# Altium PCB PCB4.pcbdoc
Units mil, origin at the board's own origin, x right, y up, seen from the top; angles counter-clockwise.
Board outline 1949.7 x 1974.5 mil, 4 copper layers (Top Layer, Inner1, Inner2, Bottom Layer); 13 components, 9 nets, 52 pads, 33 vias.
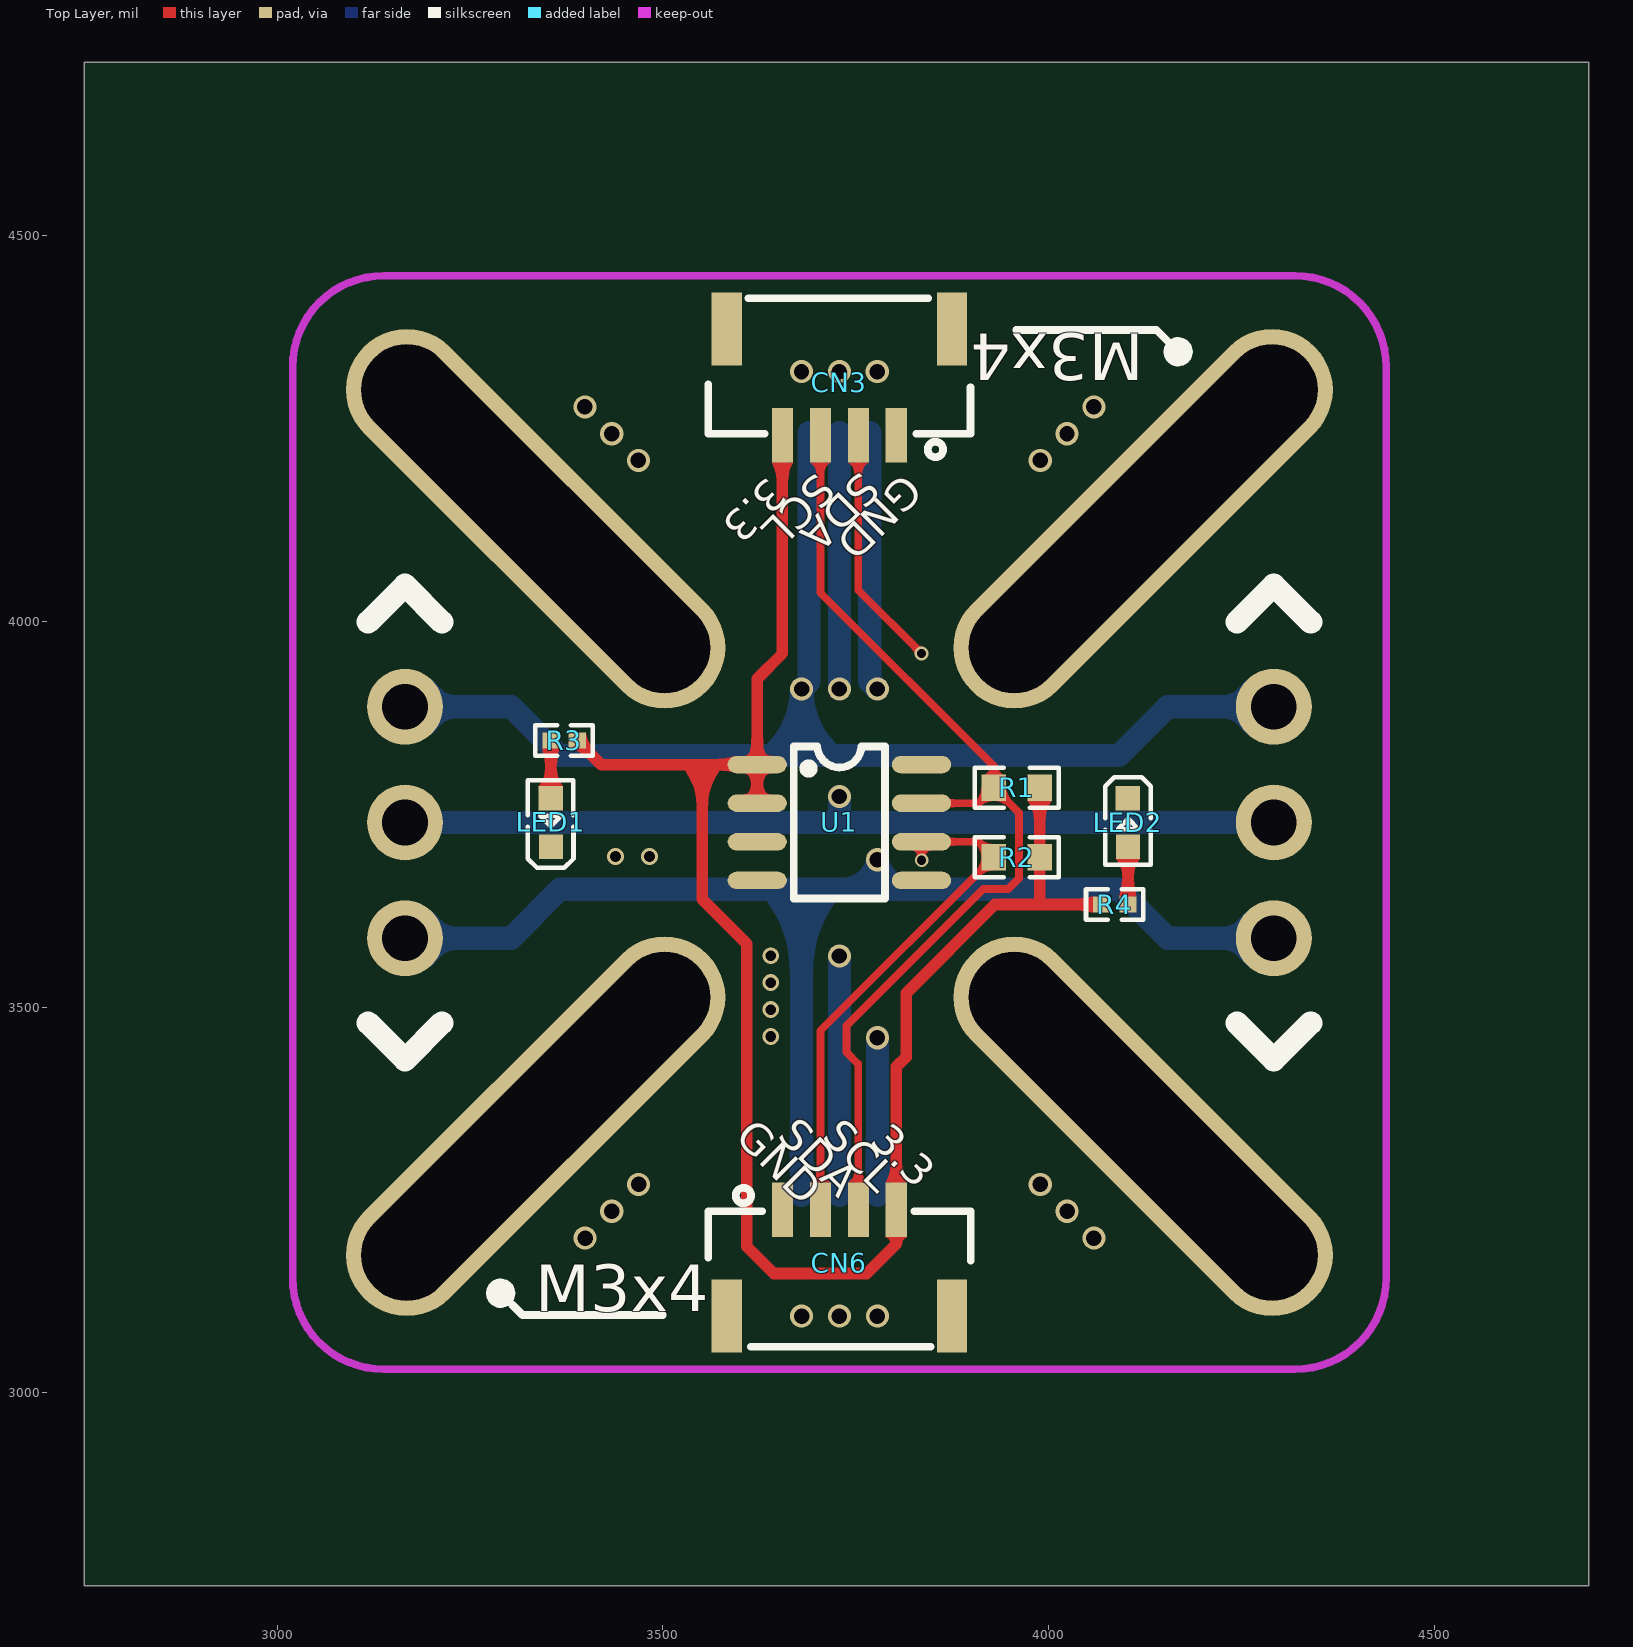
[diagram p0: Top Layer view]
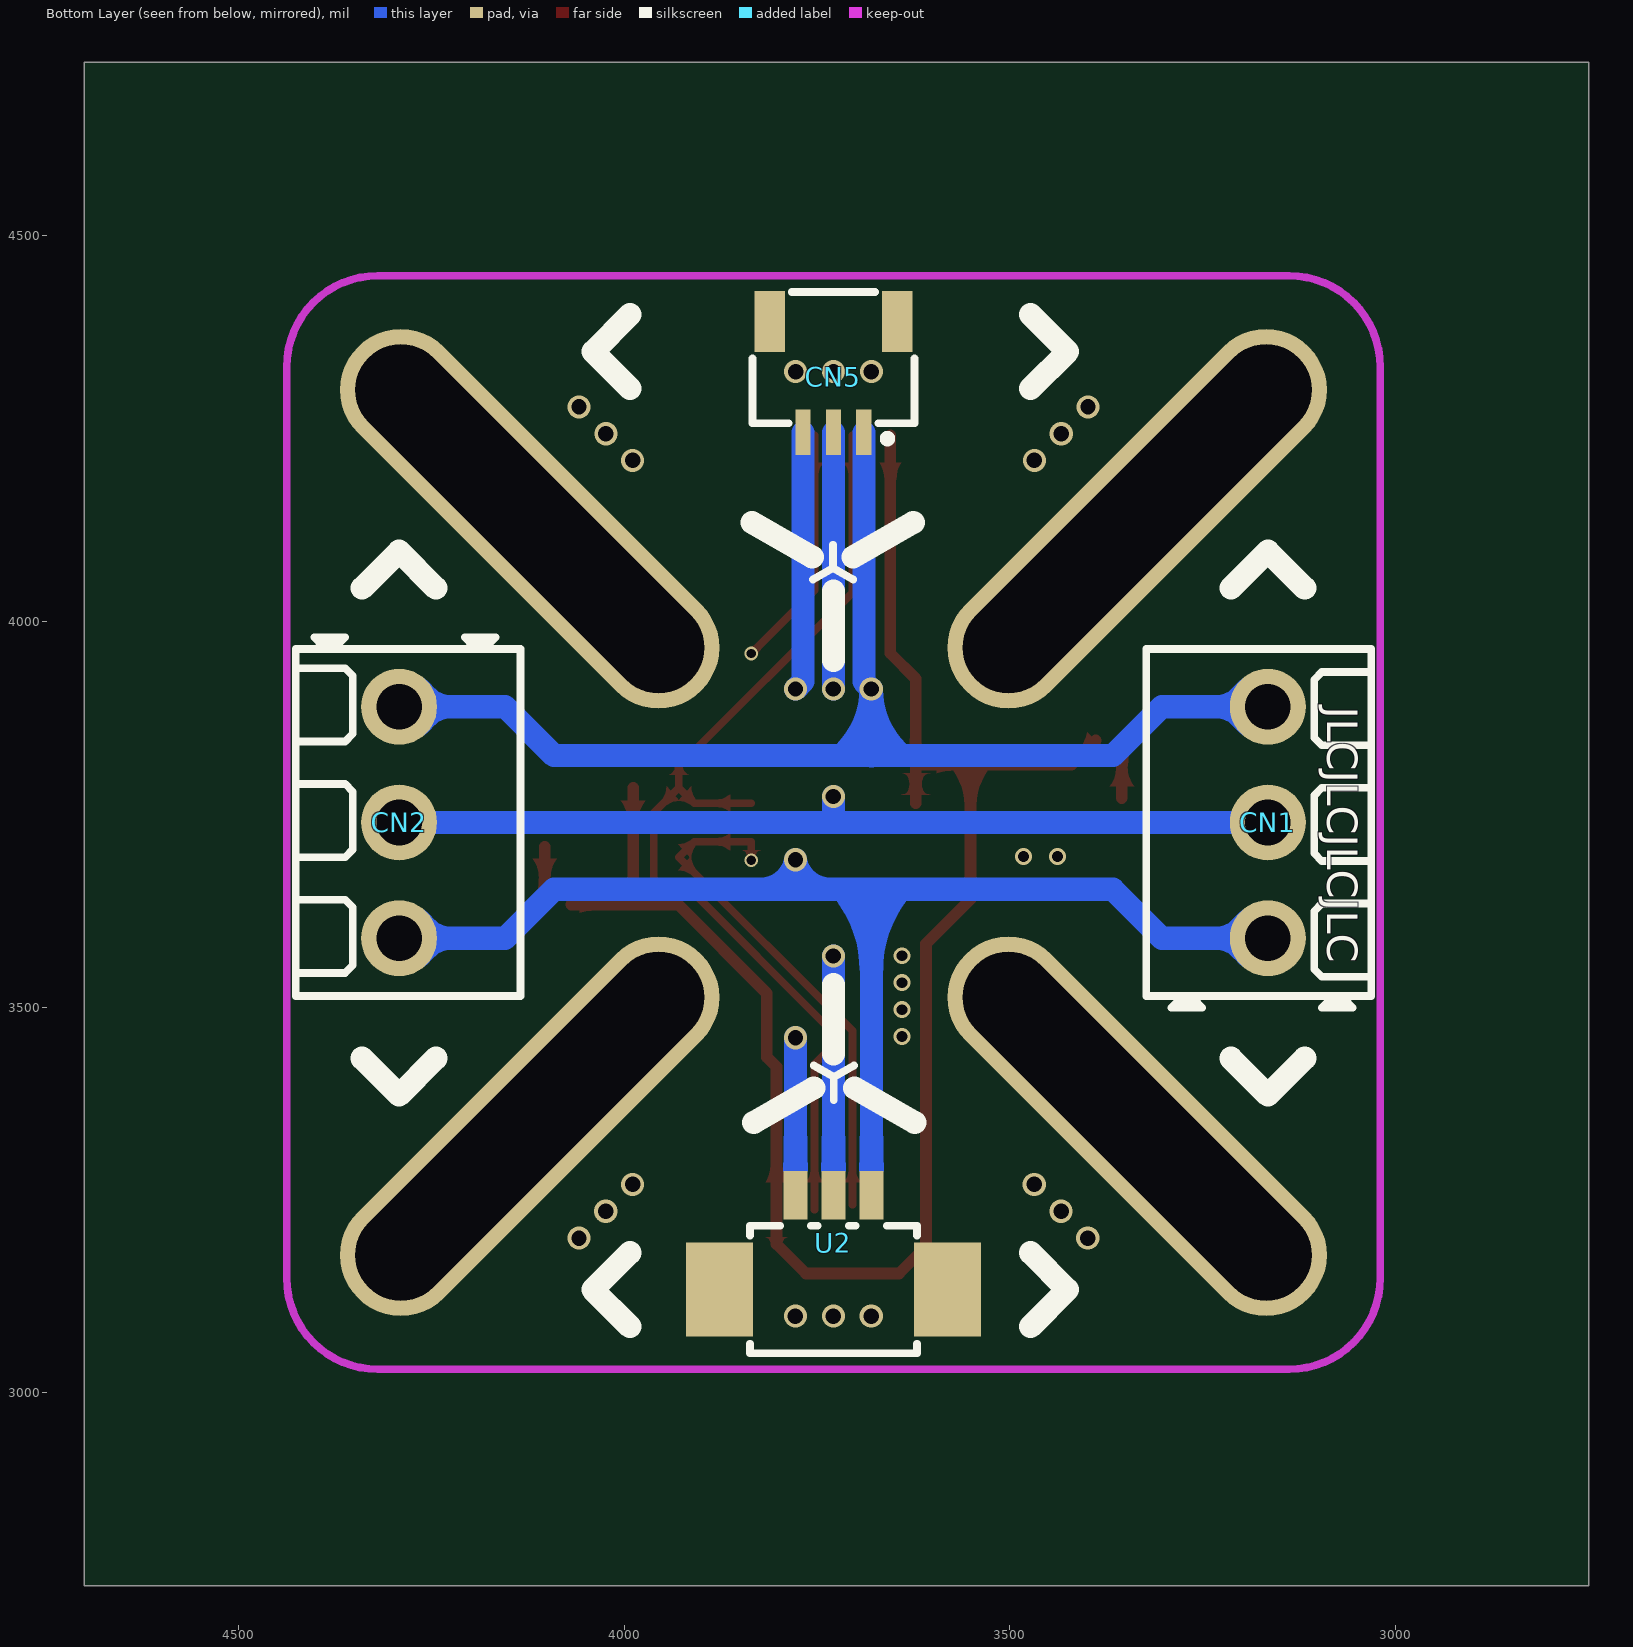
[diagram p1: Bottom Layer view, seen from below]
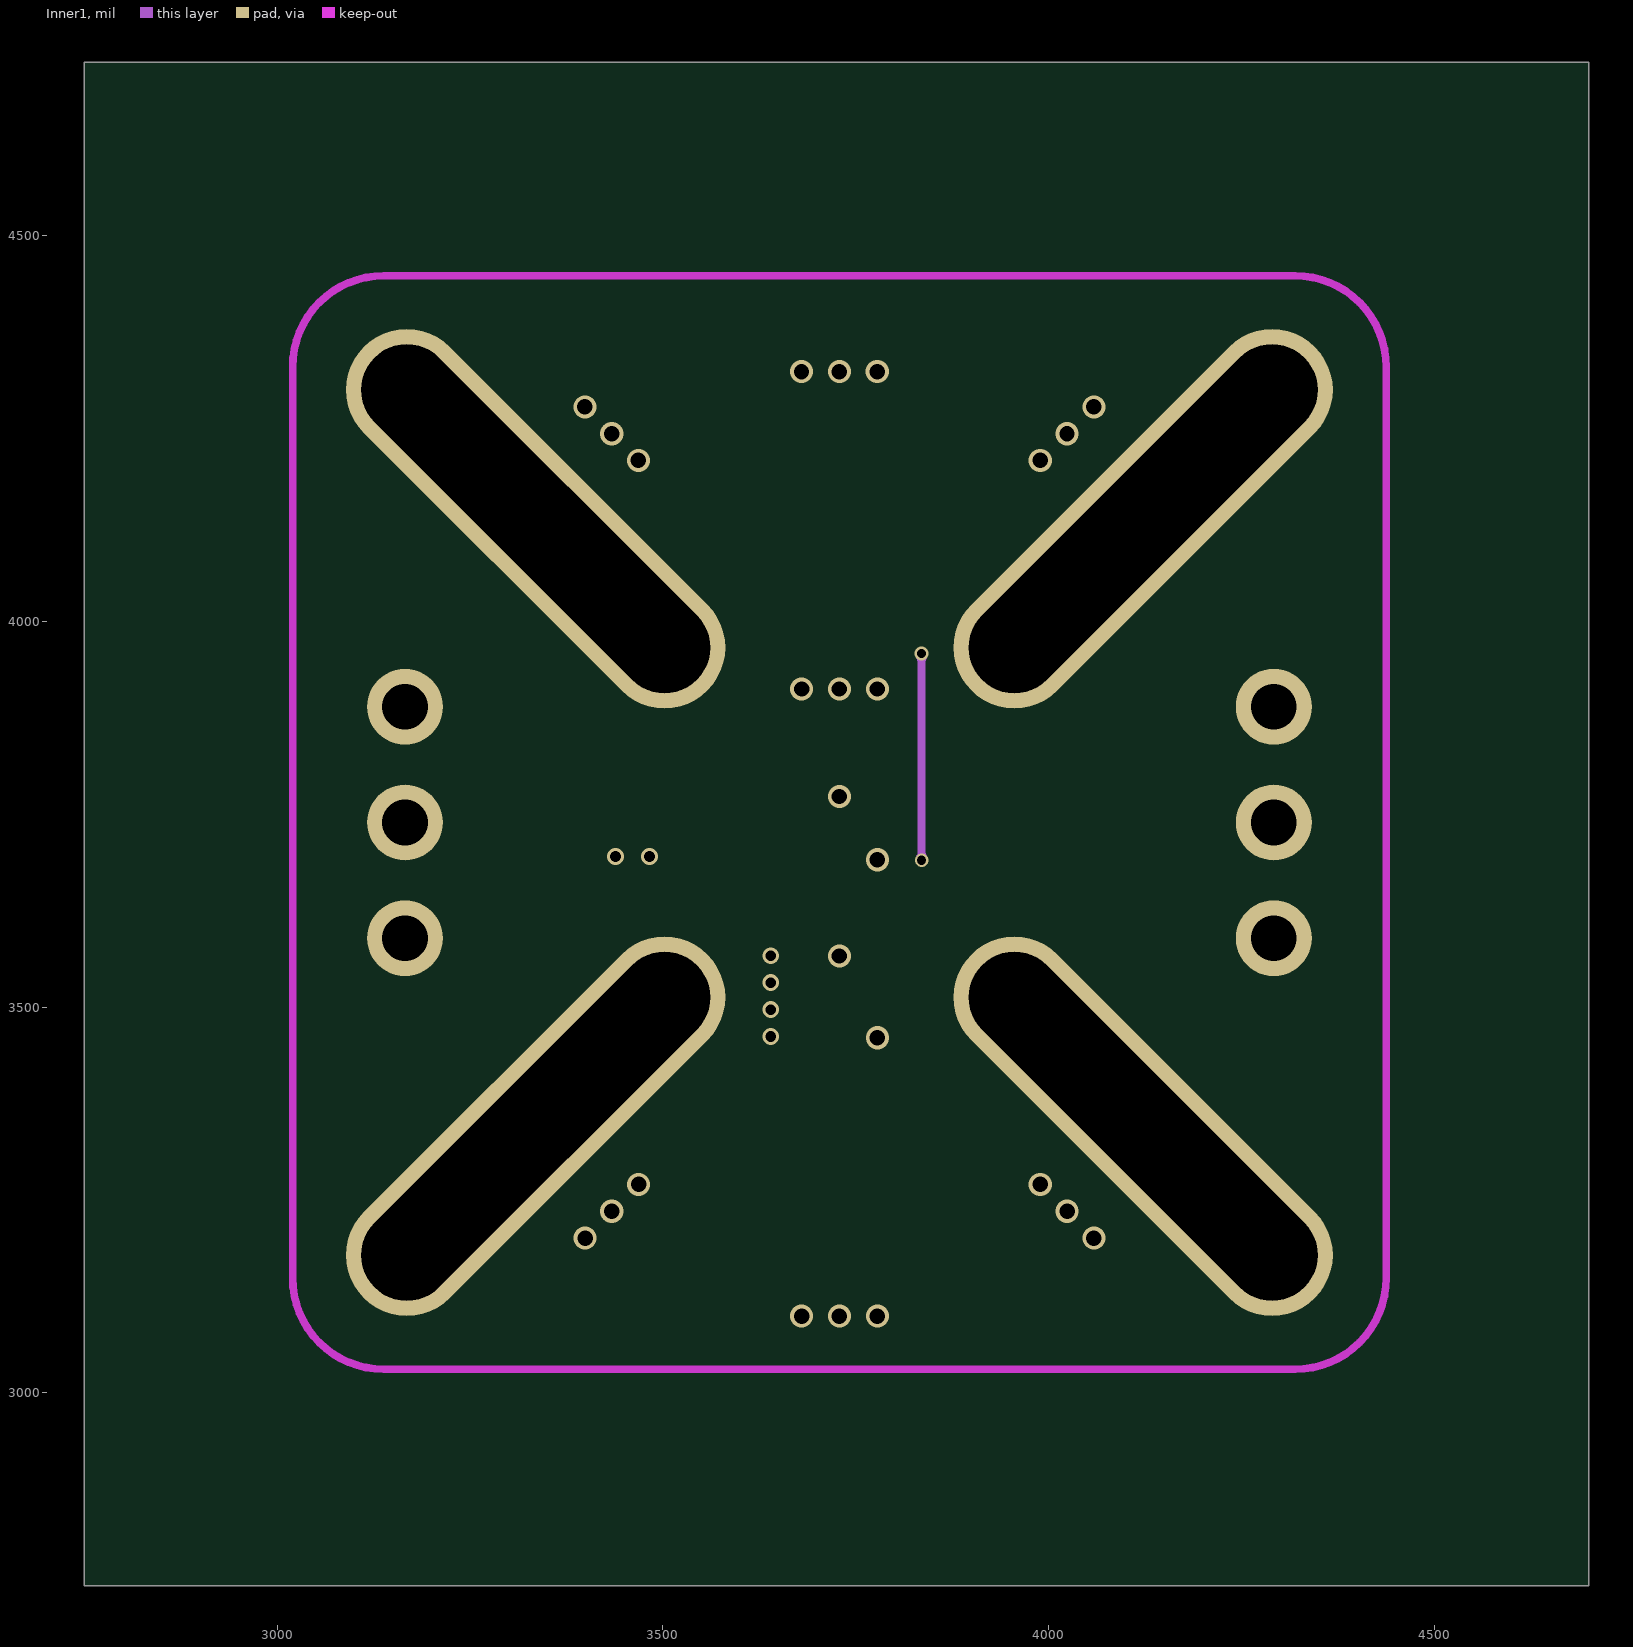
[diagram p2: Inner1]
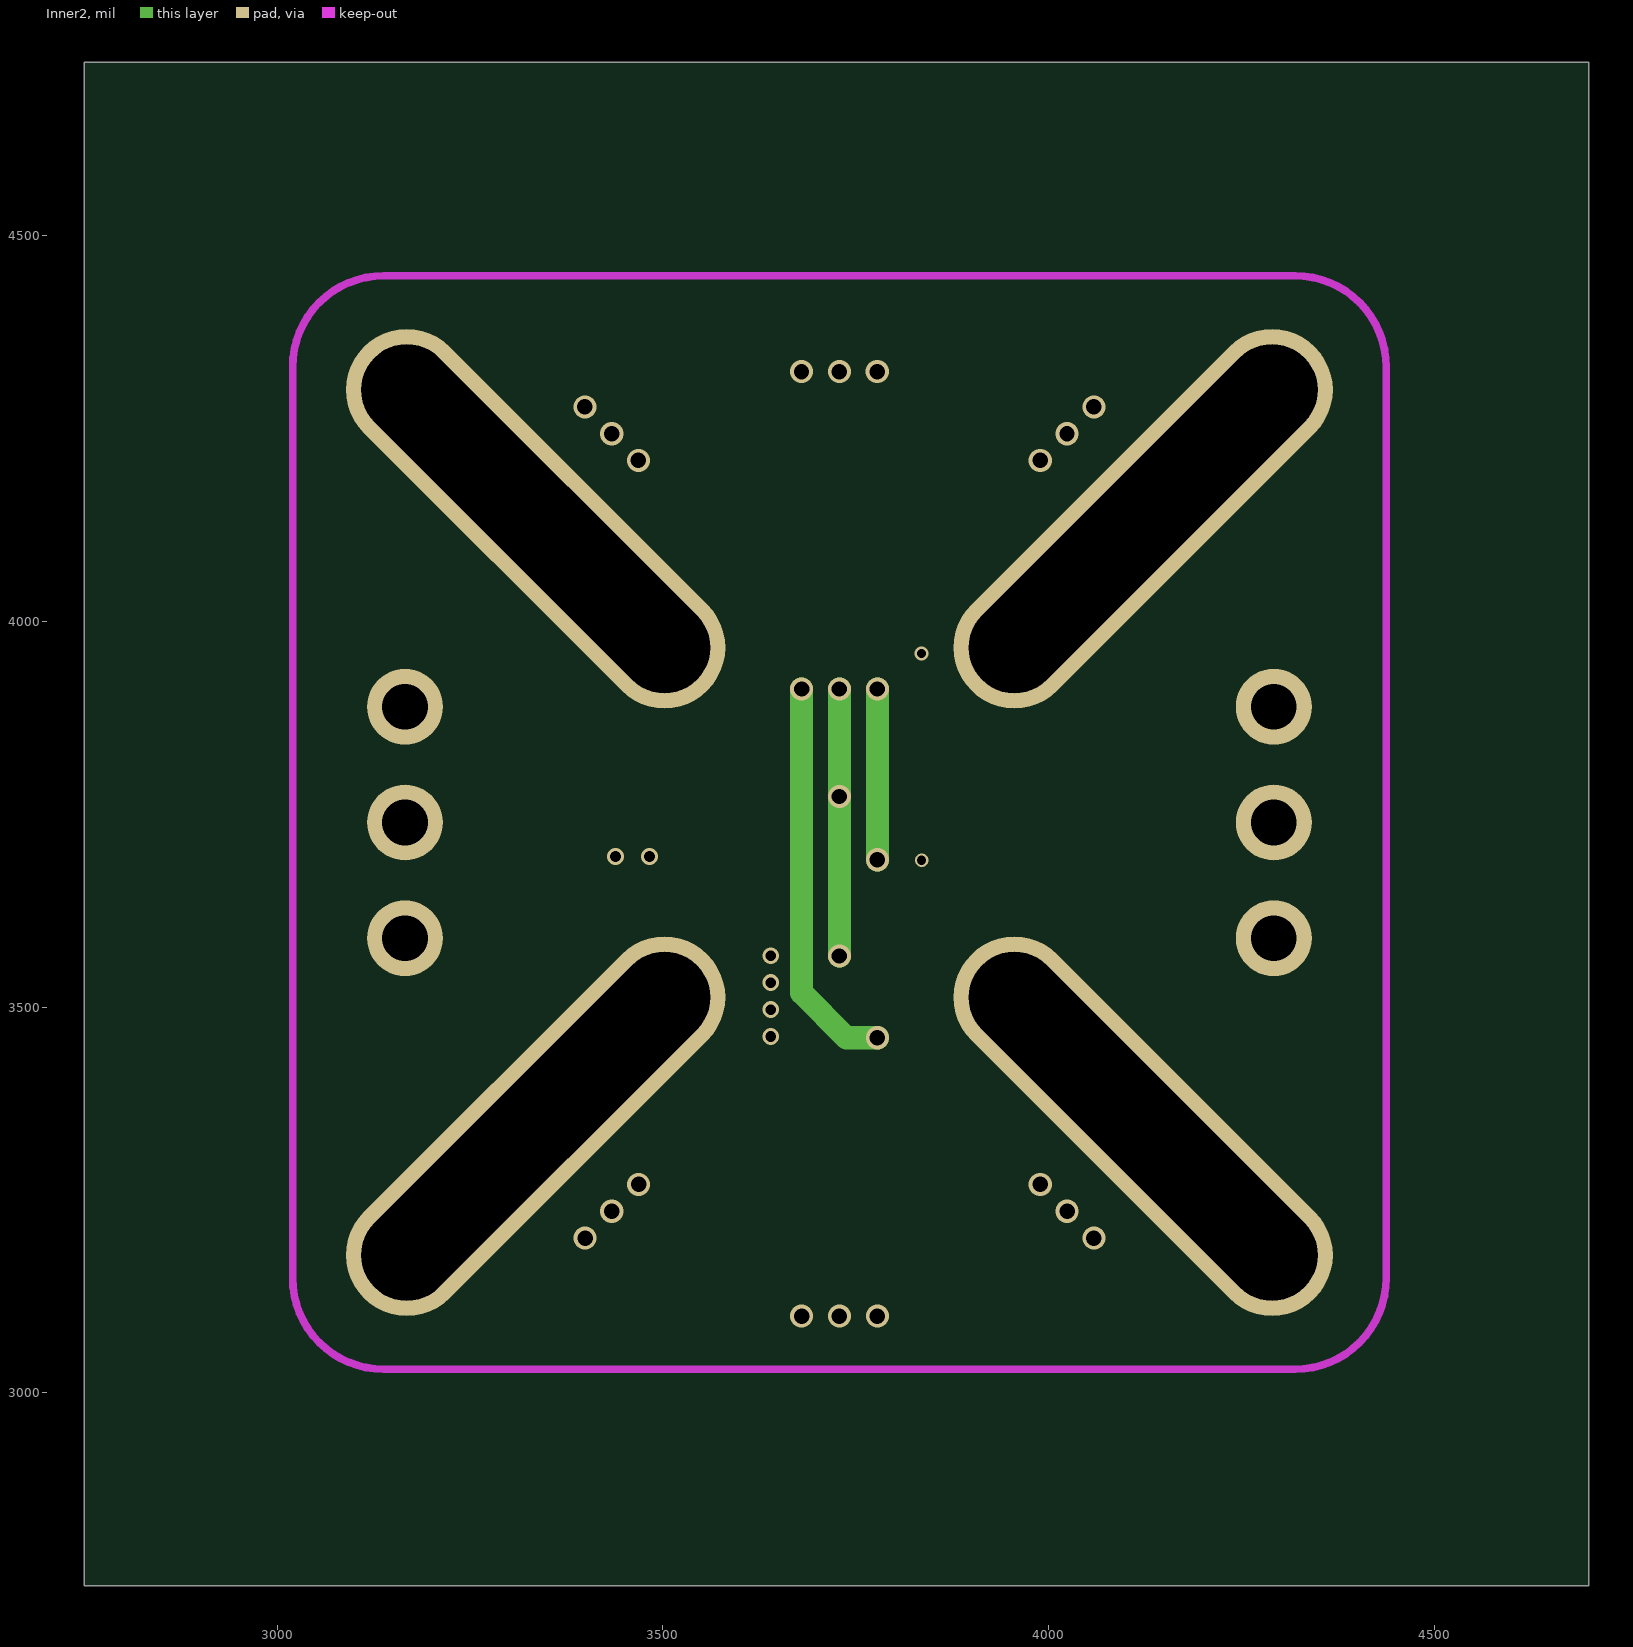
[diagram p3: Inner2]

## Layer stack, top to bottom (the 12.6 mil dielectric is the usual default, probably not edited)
Top Layer: signal copper (thickness not stored)
Dielectric: dielectric 12.6, FR-4, Dk 4.8
Inner1: signal copper (thickness not stored)
Dielectric: dielectric 12.6, FR-4, Dk 4.8
Inner2: signal copper (thickness not stored)
Dielectric: dielectric 12.6, FR-4, Dk 4.8
Bottom Layer: signal copper (thickness not stored)

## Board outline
4699.7,2750 2750,2750 2750,4724.5 4699.7,4724.5

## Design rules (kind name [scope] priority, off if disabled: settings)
BoardOutlineClearance copperThickness1oz [All] p0: genericclearance=10 ignorepadtopadclearanceinfootprint=FALSE except(0: Arc-SplitContinuation Track-SplitContinuation SMDPad-SplitContinuation THPad-SplitContinuation Via-SplitContinuation Fill-SplitContinuation Poly-SplitContinuation Region-SplitContinuation Text-SplitContinuation; 6: Track-CutoutEdge SMDPad-CutoutEdge THPad-CutoutEdge Via-CutoutEdge Region-CutoutEdge; 11.8: Track-OutlineEdge SMDPad-OutlineEdge THPad-OutlineEdge Via-OutlineEdge Fill-OutlineEdge Region-OutlineEdge Poly-OutlineEdge Text-OutlineEdge Fill-CutoutEdge)
BoardOutlineClearance copperThickness2oz [All] p0: genericclearance=10 ignorepadtopadclearanceinfootprint=FALSE except(0: Arc-SplitContinuation Track-SplitContinuation SMDPad-SplitContinuation THPad-SplitContinuation Via-SplitContinuation Fill-SplitContinuation Poly-SplitContinuation Region-SplitContinuation Text-SplitContinuation; 6: Track-CutoutEdge SMDPad-CutoutEdge THPad-CutoutEdge Via-CutoutEdge Region-CutoutEdge; 11.8: Track-OutlineEdge SMDPad-OutlineEdge THPad-OutlineEdge Via-OutlineEdge Fill-OutlineEdge Region-OutlineEdge Poly-OutlineEdge Text-OutlineEdge Fill-CutoutEdge)
Clearance copperThickness1oz [(InNet('W') OR InNet('V') OR InNet('U') OR InNet('+3.3V_1') OR InNet('SCL') OR InNet('SDA') OR InNet('DGND') OR InNet('$1N581') OR InNet('$1N584'))] p1: gap=7 ignorepadtopadclearanceinfootprint=FALSE except(4: Track-Track; 6: Track-SMDPad SMDPad-SMDPad Track-THPad SMDPad-THPad THPad-THPad Track-Via SMDPad-Via THPad-Via Via-Via SMDPad-Fill THPad-Fill Via-Fill Fill-Fill Track-Region SMDPad-Region THPad-Region Via-Region Region-Region Track-Poly SMDPad-Poly THPad-Poly Via-Poly Fill-Poly Region-Poly Poly-Poly Track-Text SMDPad-Text THPad-Text Via-Text Fill-Text Region-Text Poly-Text Text-Text; 6.9: Track-Hole SMDPad-Hole THPad-Hole Via-Hole Fill-Hole Region-Hole Poly-Hole Text-Hole Sheet-Hole; 11.8: Track-Fill Fill-Region Track-Sheet SMDPad-Sheet THPad-Sheet Via-Sheet Fill-Sheet Region-Sheet Poly-Sheet Text-Sheet)
Clearance copperThickness2oz [All] p1: gap=7 ignorepadtopadclearanceinfootprint=FALSE except(6: Track-SMDPad SMDPad-SMDPad Track-THPad SMDPad-THPad THPad-THPad Track-Via SMDPad-Via THPad-Via Via-Via SMDPad-Fill THPad-Fill Via-Fill Fill-Fill Track-Region SMDPad-Region THPad-Region Via-Region Region-Region Track-Poly SMDPad-Poly THPad-Poly Via-Poly Fill-Poly Region-Poly Poly-Poly Track-Text SMDPad-Text THPad-Text Via-Text Fill-Text Region-Text Poly-Text Text-Text; 6.9: Track-Hole SMDPad-Hole THPad-Hole Via-Hole Fill-Hole Region-Hole Poly-Hole Text-Hole Sheet-Hole; 8: Track-Track; 11.8: Track-Fill Fill-Region Track-Sheet SMDPad-Sheet THPad-Sheet Via-Sheet Fill-Sheet Region-Sheet Poly-Sheet Text-Sheet)
DiffPairsRouting differentialPair [All] p1: maxuncoupledlength=10 minlimit=6 maxlimit=6 mostfreqgap=6 toplayer_minwidth=5 toplayer_prefwidth=10 toplayer_maxwidth=100 bottomlayer_minwidth=5 bottomlayer_prefwidth=10 bottomlayer_maxwidth=100 midlayer1_minwidth=5 midlayer1_prefwidth=10 midlayer1_maxwidth=100 midlayer2_minwidth=5 midlayer2_prefwidth=10 midlayer2_maxwidth=100
PasteMaskExpansion pasteMaskExpansion [All] p1: expansion=0
PlaneConnect innerPlane [All] p1: planeconnectstyle=Relief reliefexpansion=20 reliefentries=4 reliefconductorwidth=10 reliefairgap=10
PolygonConnect copperRegion [All] p1: connectstyle=Direct reliefentries=4 reliefconductorwidth=10 polygonreliefangle="90 Angle" airgapwidth=10
RoutingVias viaSize [All] p1: viastyle="Through Hole" holewidth=12 minholewidth=11.8 maxholewidth=248 width=24 minwidth=17.7 maxwidth=393.7
SolderMaskExpansion solderMaskExpansion [All] p1: useseparateexpansions=TRUE expansion=2 expansionbottom=2
Width copperThickness1oz [All] p1: maxlimit=100 minlimit=5 preferedwidth=10
Width copperThickness2oz [All] p1: maxlimit=100 minlimit=8 preferedwidth=10

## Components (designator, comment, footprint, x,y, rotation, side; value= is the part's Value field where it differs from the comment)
CN1 "DB125-3.81-3P-RD-S" CONN-TH_3P-P3.81_L7.4-W11.4 3165.71,3739.2 r90 bottom
CN2 "DB125-3.81-3P-RD-S" CONN-TH_3P-P3.81_L7.4-W11.4 4291.69,3739.2 r270 bottom
CN3 "HC-GH-4PWT_C2845399" CONN-SMD_HC-GH-4PWT 3728.7,4310.07 r180 top
CN5 "HC-1.0-3PWT" CONN-SMD_3P-P1.0-HC-1.0-3PWT 3728.7,4316.7 r0 bottom locked
CN6 "HC-GH-4PWT_C2845399" CONN-SMD_HC-GH-4PWT 3728.7,3168.33 r0 top
LED1 "XL-1608UBC-04" LED0603-RD_BLUE 3354.68,3739.2 r90 top
LED2 "XL-1608UBC-04" LED0603-RD_BLUE 4102.72,3739.2 r270 top
R1 "0603WAF1002T5E" R0603 3958.7,3784.2 r0 top
R2 "0603WAF1002T5E" R0603 3958.7,3694.2 r0 top
R3 "FRC0402J102 TS" R0402 3371.89,3845.5 r0 top
R4 "FRC0402J102 TS" R0402 4085.51,3632.9 r180 top
U1 "AS5600-ASOT" SOIC-8_L5.0-W4.0-P1.27-LS6.0-BL 3728.7,3739.2 r270 top
U2 "532610371" CONN-TH_532610371 3728.7,3194.83 r180 bottom

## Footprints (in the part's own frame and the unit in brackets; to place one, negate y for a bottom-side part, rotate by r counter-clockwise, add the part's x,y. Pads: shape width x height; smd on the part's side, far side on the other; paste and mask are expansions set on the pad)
CONN-SMD_3P-P1.0-HC-1.0-3PWT [mm]
  rect 0.5x1.5 smd: 1(-1,1.825) 2(0,1.825) 3(1,1.825)
  rect 1x2 smd: 4(-2.1,-1.825) 5(2.1,-1.825)
  silkscreen extent -2.67,-2.79 2.67,2.16
CONN-SMD_HC-GH-4PWT [mm]
  rect 0.7x1.8 smd: 1(-1.875,1.75) 2(-0.625,1.75) 3(0.625,1.75) 4(1.875,1.75)
  rect 1x2.4 smd: 5(3.705,-1.75) 6(-3.705,-1.75)
  silkscreen extent -4.32,-2.76 4.32,2.47
CONN-TH_3P-P3.81_L7.4-W11.4 [mm]
  round 2.5 hole 1.5: 1(-3.81,0) 2(0,0) 3(3.81,0)
  silkscreen extent -6.1,-3.4 5.71,4
CONN-TH_532610371 [mm]
  rect 0.8x1.6 smd: 1(-1.25,1.55) 2(0,1.55) 3(1.25,1.55)
  rect 2.2x3.1 smd: 4(3.75,-1.55) 5(-3.75,-1.55)
  silkscreen extent -2.75,-3.65 2.75,0.55
LED0603-RD_BLUE [mil]
  rect 31.5x31.5 smd: 1(-31.5,-0.1) 2(31.5,0.1)
  silkscreen extent -59,-29 55,30
R0402 [mm]
  rect 0.566x0.54 smd: 1(-0.433,0) 2(0.433,0)
  silkscreen extent -0.94,-0.5 0.94,0.5
R0603 [mil]
  rect 31.75x34.02 smd: 1(-29.66,0) 2(29.66,0)
  silkscreen extent -55,-26 55,26
SOIC-8_L5.0-W4.0-P1.27-LS6.0-BL [mil]
  oval 22.38x76.78 smd: 1(-75,-106.5) 2(-25,-106.5) 3(25,-106.5) 4(75,-106.5) 5(75,106.5) 6(25,106.5) 7(-25,106.5) 8(-75,106.5)
  silkscreen extent -98,-59 98,59

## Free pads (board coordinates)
  oval 629.92x157.48 hole 118.11 slot 590.55 at 45 deg rot 45: 1(3335,3345.5) 1(4122.4,4132.9)
  oval 629.92x157.48 hole 118.11 slot 590.55 at 135 deg rot 135: 1(3335,4132.9) 1(4122.4,3345.5)

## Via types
v1: diameter 30, hole 20, Top Layer to Bottom Layer, 25 vias
v2: diameter 22, hole 14, Top Layer to Bottom Layer, 6 vias
v3: diameter 17.7, hole 12, Top Layer to Bottom Layer, 2 vias

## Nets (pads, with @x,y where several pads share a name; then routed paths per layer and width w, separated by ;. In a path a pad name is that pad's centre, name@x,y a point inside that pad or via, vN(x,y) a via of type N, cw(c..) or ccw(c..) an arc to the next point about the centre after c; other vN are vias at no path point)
$1N581: LED1.2 R3.1 | length 75
  Top Layer w10: LED1.2@3354.55,3770.67 LED1.2@3354.85,3770.97
  Top Layer w15: LED1.2@3354.85,3770.97 R3.1
$1N584: LED2.2 R4.1 | length 75
  Top Layer w10: R4.1 R4.1@4102.85,3633.2
  Top Layer w15: R4.1@4102.85,3633.2 LED2.2@4102.85,3707.73
+3.3V_1: CN3.4 CN6.4 R1.2 R2.2 R3.2 R4.2 U1.1 U1.2 | length 2391.7
  Top Layer w15: R3.2 3420.23,3814.2 3551.1,3814.2 ; U1.2 U1.1 ; CN3.4 3654.88,3958.28 3622.2,3925.6 U1.1 ; R1.2 R2.2 3988.36,3632.9 ; R4.2 3988.36,3632.9 ; 3551.1,3814.2 U1.1 ; 3551.1,3814.2 3551.1,3639.8 3608.8,3582.1 3608.8,3189.7 3643.8,3154.7 3764.3,3154.7 3802.52,3192.92 CN6.4 3802.52,3422.52 3815.16,3435.16 3815.16,3517.98 3930.08,3632.9 3988.36,3632.9
DGND: CN3.1 CN6.1 LED1.1 LED2.1 U1.4
  other v1: 3679.73,3099.43 3728.77,3099.43 3777.98,3099.43 3399.03,3200.58 4058.53,3200.59 3433.7,3235.26 4023.85,3235.26 3468.5,3270.06 3989.05,3270.06 3468.23,4208.46 3989.03,4208.45 3433.55,4243.14 4023.7,4243.14 3398.75,4277.93 4058.5,4277.93 3679.59,4323.51 3728.63,4323.51 3777.84,4323.51
  other v2: 3639.73,3461.7 3639.73,3496.63 3639.73,3531.55 3639.73,3566.47 3438.5,3695.1 3482.4,3695.1
SCL: CN3.3 CN6.3 R1.1 U1.7 | length 1330.7
  Top Layer w10: CN3.3 3704.09,4036.81 3929.04,3811.86 R1.1 ; CN6.3 3753.31,3426.09 3737.91,3441.49 3737.91,3475.81 3915.08,3652.98 3947.56,3652.98 3961.48,3666.91 3961.48,3751.76 R1.1 ; U1.7 3909.04,3764.2 R1.1
SDA: CN3.2 CN6.2 R2.1 U1.6 | length 1255.9
  Top Layer w10: CN6.2@3704.09,3243.89 3704.09,3469.25 R2.1 3909.04,3714.2 U1.6 v3@3835.2,3690.27 ; CN3.2 3753.31,4040.09 v3(3835.2,3958.2)
  Inner1 w10: v3@3835.2,3691.67 v3@3835.95,3692.42 ; v3(3835.2,3958.2) 3835.2,3693.17 v3@3835.95,3692.42 ; v3(3835.25,3690.22) v3@3835.95,3692.42
U: CN1.3 CN2.1 CN5.1 U2.1 | length 2322.8
  Inner2 w30: v1(3679.66,3912.19) 3679.66,3518.24 3737.7,3460.2 v1(3777.91,3460.2)
  Bottom Layer w30: CN1.3 3303.11,3889.2 3366.5,3825.81 3679.49,3825.81 ; 3679.54,3825.63 3679.73,3825.81 ; CN5.1 3689.33,3921.86 v1(3679.66,3912.19) 3679.66,3826.22 3679.49,3826.05 ; U2.1 v1(3777.91,3460.2) ; CN2.1 4154.29,3889.2 4090.9,3825.81 3679.73,3825.81 ; 3679.49,3825.81 3679.73,3825.81 ; 3679.49,3825.81 3679.49,3826.05 ; 3679.49,3826.05 3679.73,3825.81
V: CN1.2 CN2.2 CN5.2 U2.2 | length 2148.7
  Inner2 w30: v1(3728.7,3566.2) v1(3728.7,3772.9) v1(3728.7,3912.2)
  Bottom Layer w30: CN1.2 3728.7,3739.2 ; U2.2 v1(3728.7,3566.2) ; v1(3728.7,3772.9) 3728.7,3739.2 ; v1(3728.7,3912.2) CN5.2 ; CN2.2 3728.7,3739.2
W: CN1.1 CN2.3 CN5.3 U2.3 | length 2171.9
  Inner2 w30: v1(3777.9,3690.82) v1(3777.91,3912.2)
  Bottom Layer w10: 3679.49,3651.87 3680.2,3652.59
  Bottom Layer w30: CN1.1 3303.11,3589.2 3366.5,3652.59 3680.2,3652.59 3777.9,3652.59 ; U2.3 3679.49,3651.87 ; CN5.3 3768.07,3922.04 v1(3777.91,3912.2) ; v1(3777.9,3690.82) 3777.9,3652.59 ; CN2.3 4154.29,3589.2 4090.9,3652.59 3777.9,3652.59
pads on no net: CN3.5 CN3.6 CN5.4 CN5.5 CN6.5 CN6.6 U1.3 U1.5 U1.8 U2.4 U2.5

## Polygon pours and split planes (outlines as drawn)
DGND on Top Layer (solid, remove dead copper, pour order 0): 3000,4474.5 4449.7,4474.5 4449.7,3000 3000,3000
DGND on Inner1 (solid, remove dead copper): 3000,4474.5 4449.7,4474.5 4449.7,3000 3000,3000
DGND on Inner2 (solid, remove dead copper): 3000,4474.5 4449.7,4474.5 4449.7,3000 3000,3000
DGND on Bottom Layer (solid, remove dead copper, pour order 2): 3000,4474.5 4449.7,4474.5 4449.7,3000 3000,3000

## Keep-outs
Board Outline Layer:
  lines w10: 3020.04,3148.65 ccw(c3138.15,3148.65) 3138.15,3030.54 4319.25,3030.54 ccw(c4319.25,3148.65) 4437.36,3148.65 4437.36,4329.75 ccw(c4319.25,4329.75) 4319.25,4447.86 3138.15,4447.86 ccw(c3138.15,4329.75) 3020.04,4329.75 3020.04,3148.65

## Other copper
Top Layer:
  region net $1N581: 3347.35,3808.95 3362.35,3808.95 ccw(c3398.04,3808.95) 3370.33,3786.45 3338.83,3786.45 ccw(c3313.36,3808.95)
  region net $1N584: 4110.35,3669.45 4095.35,3669.45 ccw(c4060.67,3669.45) 4087.07,3691.95 4118.57,3691.95 ccw(c4145.28,3669.45)
  region net +3.3V_1: 3995.86,3744.69 3980.86,3744.69 ccw(c3946.45,3744.69) 3972.48,3767.19 4004.24,3767.19 ccw(c4030.27,3744.69)
  region net SCL: 3913.8,3761.89 3907.86,3770.09 ccw(c3886.65,3786) 3913.16,3786 3929.71,3767.19 ccw(c3929.71,3740.68)
  region net SCL: 3924.04,3811.86 3934.04,3811.86 ccw(c3945.35,3811.86) 3941.54,3801.21 3916.54,3801.21 ccw(c3912.73,3811.86)
  region net SCL: 3950.22,3770.09 3944.28,3761.89 ccw(c3928.37,3740.68) 3928.37,3767.19 3944.92,3786 ccw(c3971.43,3786)
  region net SDA: 3913.8,3671.89 3907.86,3680.09 ccw(c3886.65,3696) 3913.16,3696 3929.71,3677.19 ccw(c3929.71,3650.68)
  region net SDA: 3907.86,3708.31 3913.8,3716.51 ccw(c3929.71,3737.72) 3929.71,3711.21 3913.16,3692.4 ccw(c3886.65,3692.4)
  region net +3.3V_1: 3410.39,3834.64 3399.28,3824.54 ccw(c3373.81,3799.06) 3377.79,3834.87 3400.06,3856.13 ccw(c3435.87,3860.11)
  region net $1N581: 3362.35,3812.37 3347.35,3812.37 ccw(c3275.9,3812.37) 3343.71,3834.87 3365.98,3834.87 ccw(c3433.8,3812.37)
  region net +3.3V_1: 4034.84,3625.4 4034.84,3640.4 ccw(c4034.84,3722.84) 4057.34,3643.53 4057.34,3622.27 ccw(c4034.84,3542.97)
  region net $1N584: 4095.35,3666.03 4110.35,3666.03 ccw(c4187.98,3666.03) 4113.69,3643.53 4091.42,3643.53 ccw(c4029.1,3666.03)
  region net +3.3V_1: 3572.5,3806.7 3572.5,3821.7 3576.65,3821.86 3580.62,3822.28 3584.3,3822.87 3587.59,3823.54 3592.64,3824.81 3595,3825.39 3595,3803.01 3592.64,3803.59 3587.59,3804.86 3584.3,3805.53 3580.62,3806.12 3576.65,3806.54
  region net +3.3V_1: 3629.7,3780.51 3614.7,3780.51 3614.68,3784.71 3614.52,3788.77 3614.11,3792.57 3613.29,3795.98 3612.7,3797.49 3611.95,3798.86 3611.04,3800.06 3609.95,3801.08 3608.67,3801.9 3607.16,3802.51 3605.43,3802.88 3603.45,3803.01 3640.95,3803.01 3638.97,3802.88 3637.24,3802.51 3635.73,3801.9 3634.45,3801.08 3633.36,3800.06 3632.45,3798.86 3631.7,3797.49 3631.11,3795.98 3630.29,3792.57 3629.88,3788.77 3629.72,3784.71
  region net +3.3V_1: 3614.7,3847.89 3629.7,3847.89 3629.72,3843.69 3629.88,3839.63 3630.29,3835.83 3631.11,3832.42 3631.7,3830.91 3632.45,3829.54 3633.36,3828.34 3634.45,3827.32 3635.73,3826.5 3637.24,3825.89 3638.97,3825.52 3640.95,3825.39 3603.45,3825.39 3605.43,3825.52 3607.16,3825.89 3608.67,3826.5 3609.95,3827.32 3611.04,3828.34 3611.95,3829.54 3612.7,3830.91 3613.29,3832.42 3614.11,3835.83 3614.52,3839.63 3614.68,3843.69
  region net +3.3V_1: 3614.7,3797.89 3629.7,3797.89 3629.72,3793.69 3629.88,3789.63 3630.29,3785.83 3631.11,3782.42 3631.7,3780.91 3632.45,3779.54 3633.36,3778.34 3634.45,3777.32 3635.73,3776.5 3637.24,3775.89 3638.97,3775.52 3640.95,3775.39 3603.45,3775.39 3605.43,3775.52 3607.16,3775.89 3608.67,3776.5 3609.95,3777.32 3611.04,3778.34 3611.95,3779.54 3612.7,3780.91 3613.29,3782.42 3614.11,3785.83 3614.52,3789.63 3614.68,3793.69
  region net SCL: 3877.4,3769.2 3877.4,3759.2 3874.64,3758.93 3872.03,3758.23 3869.62,3757.24 3867.46,3756.11 3864.11,3753.98 3863.03,3753.28 3862.4,3753.01 3862.4,3775.39 3863.03,3775.12 3864.11,3774.42 3867.46,3772.29 3869.62,3771.16 3872.03,3770.17 3874.64,3769.47
  region net SDA: 3840.2,3690.27 3830.2,3690.27 3830.14,3692.65 3829.92,3694.95 3829.51,3697.1 3828.84,3699.03 3827.87,3700.66 3826.56,3701.92 3825.76,3702.38 3824.85,3702.72 3823.83,3702.94 3822.7,3703.01 3847.7,3703.01 3846.57,3702.94 3845.55,3702.72 3844.64,3702.38 3843.84,3701.92 3842.53,3700.66 3841.56,3699.03 3840.89,3697.1 3840.48,3694.95 3840.26,3692.65
  region net SDA: 3877.4,3719.2 3877.4,3709.2 3874.64,3708.93 3872.03,3708.23 3869.62,3707.24 3867.46,3706.11 3864.11,3703.98 3863.03,3703.28 3862.4,3703.01 3862.4,3725.39 3863.03,3725.12 3864.11,3724.42 3867.46,3722.29 3869.62,3721.16 3872.03,3720.17 3874.64,3719.47
  region net SDA: 3758.31,4190.73 3748.31,4190.73 ccw(c3729.56,4190.73) 3740.81,4205.73 3765.81,4205.73 ccw(c3777.06,4190.73)
  region net SCL: 3709.09,4190.73 3699.09,4190.73 ccw(c3680.34,4190.73) 3691.59,4205.73 3716.59,4205.73 ccw(c3727.84,4190.73)
  region net +3.3V_1: 3662.38,4183.23 3647.38,4183.23 ccw(c3603.93,4183.23) 3641.1,4205.73 3668.66,4205.73 ccw(c3705.83,4183.23)
  region net SDA: 3699.09,3287.67 3709.09,3287.67 ccw(c3727.84,3287.67) 3716.59,3272.67 3691.59,3272.67 ccw(c3680.34,3287.67)
  region net SCL: 3748.31,3287.67 3758.31,3287.67 ccw(c3777.06,3287.67) 3765.81,3272.67 3740.81,3272.67 ccw(c3729.56,3287.67)
  region net +3.3V_1: 3810.02,3192.92 3795.02,3192.92 ccw(c3785.6,3192.92) 3788.74,3201.8 3816.3,3201.8 ccw(c3819.44,3192.92)
  region net +3.3V_1: 3795.02,3295.17 3810.02,3295.17 ccw(c3853.47,3295.17) 3816.3,3272.67 3788.74,3272.67 ccw(c3751.57,3295.17)
  region net SDA: 3830.2,3702.23 3840.2,3702.31 3840.26,3700.65 3840.49,3699.01 3840.99,3697.46 3841.85,3696.11 3828.58,3696.04 3829.43,3697.39 3829.92,3698.94 3830.15,3700.58
  region net SDA: 3823.14,3963.18 3830.22,3970.26 3831.42,3969.12 3832.75,3968.12 3834.19,3967.38 3835.75,3967.03 3826.37,3957.65 3826.02,3959.21 3825.28,3960.65 3824.28,3961.98
  region net +3.3V_1: 3543.6,3761.7 ccw(c3468.6,3761.7) 3528.6,3806.7 3551.1,3814.2 3573.6,3806.7 ccw(c3633.6,3761.7) 3558.6,3761.7
Inner1:
  region net SDA: 3830.2,3702.23 3840.2,3702.31 3840.26,3700.65 3840.49,3699.01 3840.99,3697.46 3841.85,3696.11 3828.58,3696.04 3829.43,3697.39 3829.92,3698.94 3830.15,3700.58
  region net SDA: 3840.2,3946.15 3830.2,3946.15 3830.15,3947.81 3829.92,3949.45 3829.42,3951 3828.56,3952.35 3841.84,3952.35 3840.98,3951 3840.48,3949.45 3840.25,3947.81
Bottom Layer:
  region net W: 3232.71,3604.2 3232.71,3574.2 3229.73,3574.07 3226.98,3573.71 3224.44,3573.12 3222.08,3572.32 3219.88,3571.32 3217.8,3570.16 3215.83,3568.83 3213.93,3567.35 3210.25,3564.04 3206.55,3560.34 3202.63,3556.38 3198.26,3552.29 3198.26,3626.11 3202.63,3622.02 3206.55,3618.06 3210.25,3614.36 3213.93,3611.05 3215.83,3609.57 3217.8,3608.24 3219.88,3607.08 3222.08,3606.08 3224.44,3605.28 3226.98,3604.69 3229.73,3604.33
  region net U: 3232.71,3904.2 3232.71,3874.2 3229.73,3874.07 3226.98,3873.71 3224.44,3873.12 3222.08,3872.32 3219.88,3871.32 3217.8,3870.16 3215.83,3868.83 3213.93,3867.35 3210.25,3864.04 3206.55,3860.34 3202.63,3856.38 3198.26,3852.29 3198.26,3926.11 3202.63,3922.02 3206.55,3918.06 3210.25,3914.36 3213.93,3911.05 3215.83,3909.57 3217.8,3908.24 3219.88,3907.08 3222.08,3906.08 3224.44,3905.28 3226.98,3904.69 3229.73,3904.33
  region net U: 4224.69,3874.2 4224.69,3904.2 4227.67,3904.33 4230.42,3904.69 4232.96,3905.28 4235.32,3906.08 4237.52,3907.08 4239.6,3908.24 4241.57,3909.57 4243.47,3911.05 4247.15,3914.36 4250.85,3918.06 4254.77,3922.02 4259.14,3926.11 4259.14,3852.29 4254.77,3856.38 4250.85,3860.34 4247.15,3864.04 4243.47,3867.35 4241.57,3868.83 4239.6,3870.16 4237.52,3871.32 4235.32,3872.32 4232.96,3873.12 4230.42,3873.71 4227.67,3874.07
  region net W: 4224.69,3574.2 4224.69,3604.2 4227.67,3604.33 4230.42,3604.69 4232.96,3605.28 4235.32,3606.08 4237.52,3607.08 4239.6,3608.24 4241.57,3609.57 4243.47,3611.05 4247.15,3614.36 4250.85,3618.06 4254.77,3622.02 4259.14,3626.11 4259.14,3552.29 4254.77,3556.38 4250.85,3560.34 4247.15,3564.04 4243.47,3567.35 4241.57,3568.83 4239.6,3570.16 4237.52,3571.32 4235.32,3572.32 4232.96,3573.12 4230.42,3573.71 4227.67,3574.07
  region net W: 3664.49,3332.35 3694.49,3332.35 ccw(c5048.47,3332.35) 3695.24,3287.35 3663.74,3287.35 ccw(c2310.51,3332.35)
  region net V: 3713.7,3332.35 3743.7,3332.35 ccw(c5097.68,3332.35) 3744.45,3287.35 3712.95,3287.35 ccw(c2359.72,3332.35)
  region net U: 3762.91,3332.35 3792.91,3332.35 ccw(c5146.89,3332.35) 3793.66,3287.35 3762.16,3287.35 ccw(c2408.93,3332.35)
  region net U: 3694.66,3912.19 ccw(c3794.58,3912.19) 3724.66,3840.81 3679.61,3825.81 3634.66,3840.81 ccw(c3564.74,3912.19) 3664.66,3912.19
  region net W: 3694.49,3547.59 cw(c3844.49,3547.59) 3724.49,3637.59 3680.2,3652.59 3634.49,3637.59 cw(c3514.49,3547.59) 3664.49,3547.59
  region net W: 3762.9,3690.82 cw(c3732.9,3698.57) 3732.9,3667.59 3777.9,3652.59 3822.9,3667.59 cw(c3822.9,3698.57) 3792.9,3690.82

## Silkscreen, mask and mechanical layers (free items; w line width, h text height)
Top Silkscreen Layer:
  circle w8: c3289.69,3129.1 r15
  circle w8: c3289.69,3129.1 r8
  circle w8: c4167.71,4349.3 r15
  circle w8: c4167.71,4349.3 r8
  lines w10: 3289.69,3129.1 3317.97,3100.82 3499.6,3100.82 ; 3957.8,4377.58 4139.43,4377.58 4167.71,4349.3
  lines w30: 3117.87,3479.55 3165.71,3431.72 3213.54,3479.55 ; 3117.87,3998.85 3165.71,4046.68 3213.54,3998.85 ; 4243.86,3479.55 4291.69,3431.72 4339.53,3479.55 ; 4243.86,3998.85 4291.69,4046.68 4339.53,3998.85
  text "M3x4" at 4123,4372.6 h60 r180
  text "SDA" at 3756.36,4195.51 h40 r225
  text "SCL" at 3698.7,4194.38 h40 r225
  text "GND" at 3811.36,4193.99 h40 r225
  text "3.3" at 3636.09,4188.37 h40 r225
  text "SDA" at 3646.61,3331.76 h40 r315
  text "SCL" at 3704.37,3330.63 h40 r315
  text "GND" at 3591.57,3330.24 h40 r315
  text "3.3" at 3766.97,3324.62 h40 r315
  text "M3x4" at 3334.4,3105.8 h60
Bottom Silkscreen Layer:
  lines w10: 3702.22,3424.2 3728.2,3409.2 ; 3703.2,4054.2 3729.18,4069.2 ; 3728.2,3379.2 3728.2,3409.2 ; 3729.18,4099.2 3729.18,4069.2 ; 3754.18,3424.2 3728.2,3409.2 ; 3755.16,4054.2 3729.18,4069.2
  lines w30: 3117.89,3433.71 3165.72,3385.88 3213.55,3433.71 ; 3117.89,4043.01 3165.72,4090.84 3213.55,4043.01 ; 3473.16,4301.75 3425.33,4349.58 3473.16,4397.42 ; 3473.26,3085.97 3425.43,3133.8 3473.26,3181.64 ; 3623.3,3350.22 3701.24,3395.22 ; 3625.28,4128.18 3703.22,4083.18 ; 3728.7,3439.22 3728.7,3529.22 ; 3728.68,3949.18 3728.68,4039.18 ; 3754.17,3395.22 3832.11,3350.22 ; 3756.15,4083.18 3834.09,4128.18 ; 3992.46,4301.75 4040.29,4349.58 3992.46,4397.42 ; 3992.56,3085.97 4040.39,3133.8 3992.56,3181.64 ; 4243.87,3433.71 4291.7,3385.88 4339.54,3433.71 ; 4243.87,4043.01 4291.7,4090.84 4339.54,4043.01
  text "JLCJLCJLCJLC" at 3088.7,3889.2 h39.37 r90
Bottom Solder Mask Layer:
  drawing of 20 lines, arcs and shapes, not listed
